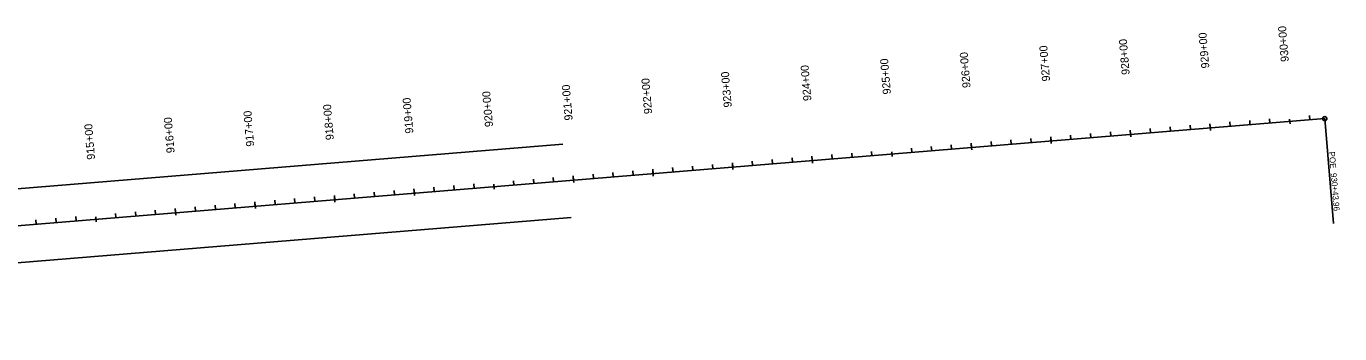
# Model space of a CAD drawing. Extents: x 14448949 to 14455476, y 8570587 to 8573998.
# Drawn here: x 14453831 to 14455476, y 8570862 to 8571248 of the extents above; entities that cross this region are included whole.
import ezdxf

# ---------------------------------------------------------------- set-up
doc = ezdxf.new("R2010")
doc.units = 0
for name, color, linetype in [('Alignment', 7, 'Continuous'), ('TextAlignment', 7, 'Continuous'), ('TextAlignmentLrg', 7, 'Continuous'), ('TextAlignmentSml', 7, 'Continuous'), ('TextNonPlot', 7, 'Continuous')]:
    doc.layers.add(name, color=color, linetype=linetype)

msp = doc.modelspace()

# ---------------------------------------------------------------- linework, layer by layer
at = {"layer": 'Alignment'}
for p, q in [((14454506.7, 8571054.2), (14455457, 8571132.1)), ((14452734, 8570908.9), (14454506.7, 8571054.2)), ((14452734, 8570908.9), (14454506.7, 8571054.2))]:
    msp.add_line(p, q, dxfattribs=at)
at = {"layer": 'TextAlignment'}
for p in [(14455457, 8571132.1), (14455467.8, 8571000.6)]:
    msp.add_line(p, (14455467.8, 8571000.6), dxfattribs=at)
msp.add_circle((14455457, 8571132.1), 2.67, dxfattribs=at)
at = {"layer": 'TextAlignmentLrg'}
for p, q in [((14455313.5, 8571120.4), (14455313.1, 8571125.8)), ((14455412.9, 8571131.6), (14455413.4, 8571125.5)), ((14455114.2, 8571104), (14455113.7, 8571109.5)), ((14455213.8, 8571112.2), (14455213.4, 8571117.7)), ((14455014.5, 8571095.9), (14455014.1, 8571101.3)), ((14454715.5, 8571071.3), (14454715.1, 8571076.8)), ((14454815.2, 8571079.5), (14454814.7, 8571085)), ((14454914.6, 8571090.7), (14454915.1, 8571084.6)), ((14454516.2, 8571055), (14454515.7, 8571060.4)), ((14454615.9, 8571063.2), (14454615.4, 8571068.6)), ((14454316.9, 8571038.7), (14454316.4, 8571044.1)), ((14454416.3, 8571049.9), (14454416.8, 8571043.8)), ((14454117.5, 8571022.3), (14454117.1, 8571027.7)), ((14454217.2, 8571030.5), (14454216.7, 8571035.9)), ((14454017.9, 8571014.1), (14454017.4, 8571019.6)), ((14453917.9, 8571009), (14453918.4, 8571002.9))]:
    msp.add_line(p, q, dxfattribs=at)
at = {"layer": 'TextAlignmentSml'}
for p, q in [((14455338.4, 8571122.4), (14455338, 8571127.9)), ((14455363.3, 8571124.5), (14455362.9, 8571129.9)), ((14455388.3, 8571126.5), (14455387.8, 8571132)), ((14455412.9, 8571131.6), (14455413.4, 8571125.5)), ((14455438.1, 8571130.6), (14455437.7, 8571136)), ((14455139.1, 8571106.1), (14455138.7, 8571111.5)), ((14455164, 8571108.1), (14455163.6, 8571113.6)), ((14455188.9, 8571110.2), (14455188.5, 8571115.6)), ((14455213.6, 8571115.3), (14455214.1, 8571109.2)), ((14455238.8, 8571114.3), (14455238.3, 8571119.7)), ((14455263.7, 8571116.3), (14455263.2, 8571121.7)), ((14455288.6, 8571118.3), (14455288.2, 8571123.8)), ((14455313.3, 8571123.4), (14455313.8, 8571117.3)), ((14454939.8, 8571089.7), (14454939.3, 8571095.2)), ((14454964.7, 8571091.8), (14454964.2, 8571097.2)), ((14454989.6, 8571093.8), (14454989.2, 8571099.3)), ((14455014.3, 8571098.9), (14455014.8, 8571092.8)), ((14455039.4, 8571097.9), (14455039, 8571103.3)), ((14455064.4, 8571100), (14455063.9, 8571105.4)), ((14455089.3, 8571102), (14455088.8, 8571107.4)), ((14455113.9, 8571107.1), (14455114.4, 8571101)), ((14454740.4, 8571073.4), (14454740, 8571078.8)), ((14454765.4, 8571075.4), (14454764.9, 8571080.9)), ((14454790.3, 8571077.5), (14454789.8, 8571082.9)), ((14454814.9, 8571082.6), (14454815.4, 8571076.5)), ((14454840.1, 8571081.6), (14454839.7, 8571087)), ((14454865, 8571083.6), (14454864.6, 8571089)), ((14454889.9, 8571085.6), (14454889.5, 8571091.1)), ((14454914.6, 8571090.7), (14454915.1, 8571084.6)), ((14454541.1, 8571057), (14454540.7, 8571062.5)), ((14454566, 8571059.1), (14454565.6, 8571064.5)), ((14454590.9, 8571061.1), (14454590.5, 8571066.6)), ((14454615.6, 8571066.2), (14454616.1, 8571060.1)), ((14454640.8, 8571065.2), (14454640.3, 8571070.7)), ((14454665.7, 8571067.3), (14454665.2, 8571072.7)), ((14454690.6, 8571069.3), (14454690.2, 8571074.7)), ((14454715.3, 8571074.4), (14454715.8, 8571068.3)), ((14454341.8, 8571040.7), (14454341.3, 8571046.1)), ((14454366.7, 8571042.7), (14454366.2, 8571048.2)), ((14454391.6, 8571044.8), (14454391.2, 8571050.2)), ((14454416.3, 8571049.9), (14454416.8, 8571043.8)), ((14454441.4, 8571048.9), (14454441, 8571054.3)), ((14454466.4, 8571050.9), (14454465.9, 8571056.4)), ((14454491.3, 8571053), (14454490.8, 8571058.4)), ((14454515.9, 8571058), (14454516.4, 8571052)), ((14454092.6, 8571020.3), (14454092.2, 8571025.7)), ((14454142.4, 8571024.4), (14454142, 8571029.8)), ((14454167.4, 8571026.4), (14454166.9, 8571031.8)), ((14454192.3, 8571028.4), (14454191.8, 8571033.9)), ((14454216.9, 8571033.5), (14454217.4, 8571027.4)), ((14454242.1, 8571032.5), (14454241.7, 8571038)), ((14454267, 8571034.6), (14454266.6, 8571040)), ((14454291.9, 8571036.6), (14454291.5, 8571042.1)), ((14454316.6, 8571041.7), (14454317.1, 8571035.6)), ((14453893.3, 8571003.9), (14453892.8, 8571009.4)), ((14453943.1, 8571008), (14453942.7, 8571013.4)), ((14453968, 8571010), (14453967.6, 8571015.5)), ((14453992.9, 8571012.1), (14453992.5, 8571017.5)), ((14454017.6, 8571017.2), (14454018.1, 8571011.1)), ((14454042.8, 8571016.2), (14454042.3, 8571021.6)), ((14454067.7, 8571018.2), (14454067.3, 8571023.7)), ((14454117.3, 8571025.4), (14454117.8, 8571019.3)), ((14453843.4, 8570999.8), (14453843, 8571005.3)), ((14453868.4, 8571001.9), (14453867.9, 8571007.3)), ((14453917.9, 8571009), (14453918.4, 8571002.9))]:
    msp.add_line(p, q, dxfattribs=at)
at = {"layer": 'TextNonPlot'}
for p, q in [((14452731.4, 8570955.1), (14454502.9, 8571100.3)), ((14452736.6, 8570862.5), (14454513.1, 8571008.3))]:
    msp.add_line(p, q, dxfattribs=at)

# ---------------------------------------------------------------- texts
at = {"layer": 'TextAlignment'}
for s, p in [('POE ', (14455462.1, 8571090.4)), ('930+43.96', (14455464.3, 8571063.6))]:
    msp.add_text(s, height=7.5, rotation=274.688, dxfattribs=at).set_placement(p)
at = {"layer": 'TextAlignmentLrg'}
for s, p in [('930+00', (14455412, 8571203.7)), ('925+00', (14454913.7, 8571162.9)), ('920+00', (14454415.4, 8571122)), ('915+00', (14453917.1, 8571081.1))]:
    msp.add_text(s, height=10.02, rotation=94.688, dxfattribs=at).set_placement(p)
at = {"layer": 'TextAlignmentSml'}
for s, p in [('929+00', (14455312.4, 8571195.5)), ('930+00', (14455412, 8571203.7)), ('927+00', (14455113, 8571179.2)), ('928+00', (14455212.7, 8571187.4)), ('925+00', (14454913.7, 8571162.9)), ('926+00', (14455013.4, 8571171)), ('923+00', (14454714.4, 8571146.5)), ('924+00', (14454814.1, 8571154.7)), ('921+00', (14454515.1, 8571130.2)), ('922+00', (14454614.7, 8571138.3)), ('919+00', (14454315.7, 8571113.8)), ('920+00', (14454415.4, 8571122)), ('917+00', (14454116.4, 8571097.5)), ('918+00', (14454216.1, 8571105.6)), ('915+00', (14453917.1, 8571081.1)), ('916+00', (14454016.7, 8571089.3))]:
    msp.add_text(s, height=10.02, rotation=94.688, dxfattribs=at).set_placement(p)

doc.saveas('drawing.dxf')
